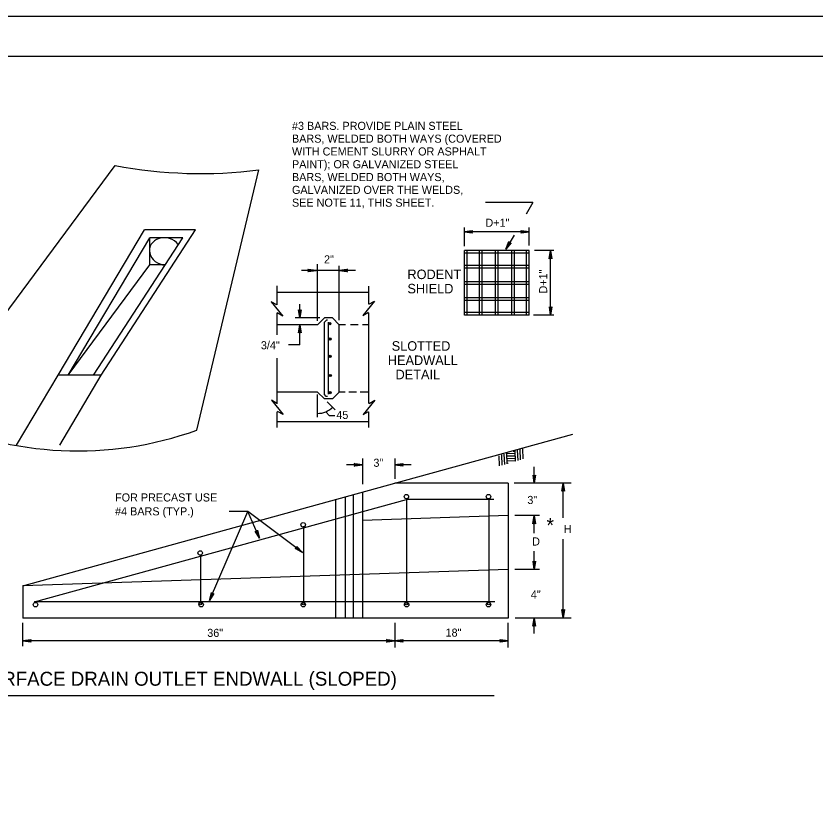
# Model space of a CAD drawing. Extents: x 638877 to 639960, y 297341 to 299123.
# Drawn here: x 639038.7 to 639335.5, y 298830 to 299123.3 of the extents above; entities that cross this region are included whole.
import ezdxf

# ---------------------------------------------------------------- set-up
doc = ezdxf.new("R2010")
doc.units = 0
for name, color, linetype in [('1', 7, 'Continuous'), ('2', 7, 'Continuous'), ('3', 7, 'Continuous'), ('PLT-BNDY', 7, 'Continuous')]:
    doc.layers.add(name, color=color, linetype=linetype)

msp = doc.modelspace()

# ---------------------------------------------------------------- linework, layer by layer
at = {"layer": '1'}
for p, q in [((639006.2, 298974.27), (639075.47, 299067.79)), ((639105.8, 298969.55), (639128.75, 299066.15)), ((639054.33, 298989.94), (639086.33, 299043.94)), ((639070.33, 298989.94), (639105.34, 299043.94)), ((639058.11, 298989.94), (639088.33, 299040.94)), ((639067.42, 298989.94), (639100.55, 299040.94)), ((639210.58, 299036.24), (639210.58, 299012.24)), ((639211.58, 299036.24), (639211.58, 299012.24)), ((639216.58, 299012.24), (639216.58, 299036.24)), ((639217.58, 299012.24), (639217.58, 299036.24)), ((639222.58, 299036.24), (639222.58, 299012.24)), ((639223.58, 299036.24), (639223.58, 299012.24)), ((639058.11, 298989.94), (639088.33, 299030.94)), ((639205.08, 299030.74), (639229.08, 299030.74)), ((639205.08, 299029.74), (639229.08, 299029.74)), ((639205.08, 299024.74), (639229.08, 299024.74)), ((639205.08, 299023.74), (639229.08, 299023.74)), ((639205.08, 299018.74), (639229.08, 299018.74)), ((639205.08, 299017.74), (639229.08, 299017.74)), ((639038.92, 298963.94), (639054.33, 298989.94)), ((639054.92, 298963.94), (639070.33, 298989.94)), ((639179.28, 298949.81), (639245.32, 298968)), ((639219.74, 298960.63), (639219.9, 298956.81)), ((639220.7, 298960.92), (639220.86, 298957.1)), ((639223.8, 298960.75), (639220.7, 298960.83)), ((639223.76, 298961.64), (639223.19, 298961.66)), ((639223.73, 298961.82), (639223.88, 298958)), ((639224.68, 298962.1), (639224.84, 298958.28)), ((639225.64, 298962.38), (639225.8, 298958.56)), ((639226.6, 298962.67), (639226.76, 298958.85)), ((639217.83, 298960.07), (639217.98, 298956.31)), ((639218.78, 298960.35), (639218.94, 298956.53)), ((639223.84, 298959.85), (639220.74, 298959.94)), ((639223.88, 298958.96), (639220.78, 298959.03)), ((639223.91, 298958.06), (639220.81, 298958.14)), ((639221.31, 298957.23), (639220.85, 298957.24)), ((639041.28, 298911.81), (639179.28, 298949.81)), ((639045.64, 298905.81), (639183.56, 298943.79))]:
    msp.add_line(p, q, dxfattribs=at)
for points in [[(639703.19, 298544.28), (639703.19, 299108.28), (638917.19, 299108.28), (638917.19, 298544.28), (639703.19, 298544.28), (639703.19, 298570.64), (639503.19, 298570.64), (639503.19, 298635.32), (639703.19, 298635.32), (639703.19, 298664.28), (639503.19, 298664.28), (639503.19, 298544.28), (639581.99, 298544.28), (639581.99, 298570.64), (639581.99, 298544.28), (639658.99, 298544.28), (639658.99, 298570.64), (639658.99, 298558.33), (639703.19, 298558.33)], [(639135.43, 299016.01), (639133.38, 299017.14), (639137.68, 299011.81), (639135.63, 299013.04)], [(639169.65, 299016.32), (639171.7, 299017.45), (639167.4, 299012.11), (639169.45, 299013.35)], [(639135.53, 298979.5), (639133.48, 298980.63), (639137.78, 298975.3), (639135.73, 298976.53)], [(639169.75, 298979.5), (639171.8, 298980.63), (639167.5, 298975.3), (639169.55, 298976.53)]]:
    msp.add_lwpolyline(points, dxfattribs=at)
for centre, radius in [((639155.12, 299009.11), 0.426), ((639155.12, 299009.11), 0.396), ((639155.12, 299009.11), 0.366), ((639155.12, 299009.11), 0.335), ((639155.12, 299009.11), 0.305), ((639155.12, 299009.11), 0.275), ((639155.12, 299009.11), 0.245), ((639155.12, 299009.11), 0.214), ((639155.12, 299009.11), 0.184), ((639155.12, 299009.11), 0.154), ((639155.12, 299009.11), 0.123), ((639155.12, 299009.11), 0.0932), ((639155.12, 299009.11), 0.063), ((639155.12, 299009.11), 0.0327), ((639155.22, 299003.37), 0.426), ((639155.22, 299003.37), 0.396), ((639155.22, 299003.37), 0.366), ((639155.22, 299003.37), 0.335), ((639155.22, 299003.37), 0.305), ((639155.22, 299003.37), 0.275), ((639155.22, 299003.37), 0.245), ((639155.22, 299003.37), 0.214), ((639155.22, 299003.37), 0.184), ((639155.22, 299003.37), 0.154), ((639155.22, 299003.37), 0.123), ((639155.22, 299003.37), 0.0932), ((639155.22, 299003.37), 0.063), ((639155.22, 299003.37), 0.0327), ((639155.22, 298996.91), 0.426), ((639155.22, 298996.91), 0.396), ((639155.22, 298996.91), 0.366), ((639155.22, 298996.91), 0.335), ((639155.22, 298996.91), 0.305), ((639155.22, 298996.91), 0.275), ((639155.22, 298996.91), 0.245), ((639155.22, 298996.91), 0.214), ((639155.22, 298996.91), 0.184), ((639155.22, 298996.91), 0.154), ((639155.22, 298996.91), 0.123), ((639155.22, 298996.91), 0.0932), ((639155.22, 298996.91), 0.063), ((639155.22, 298996.91), 0.0327), ((639155.33, 298989.83), 0.426), ((639155.33, 298989.83), 0.396), ((639155.33, 298989.83), 0.366), ((639155.33, 298989.83), 0.335), ((639155.33, 298989.83), 0.305), ((639155.33, 298989.83), 0.275), ((639155.33, 298989.83), 0.245), ((639155.33, 298989.83), 0.214), ((639155.33, 298989.83), 0.184), ((639155.33, 298989.83), 0.154), ((639155.33, 298989.83), 0.123), ((639155.33, 298989.83), 0.0932), ((639155.33, 298989.83), 0.063), ((639155.33, 298989.83), 0.0327), ((639155.22, 298983.48), 0.426), ((639155.22, 298983.48), 0.396), ((639155.22, 298983.48), 0.366), ((639155.22, 298983.48), 0.335), ((639155.22, 298983.48), 0.305), ((639155.22, 298983.48), 0.275), ((639155.22, 298983.48), 0.245), ((639155.22, 298983.48), 0.214), ((639155.22, 298983.48), 0.184), ((639155.22, 298983.48), 0.154), ((639155.22, 298983.48), 0.123), ((639155.22, 298983.48), 0.0932), ((639155.22, 298983.48), 0.063), ((639155.22, 298983.48), 0.0327), ((639183.56, 298944.89), 0.83), ((639214.01, 298944.89), 0.83), ((639145.25, 298934.42), 0.83), ((639107.06, 298923.96), 0.83), ((639045.96, 298904.75), 0.83), ((639107.42, 298904.75), 0.83), ((639107.14, 298905.24), 0.538), ((639145.29, 298904.75), 0.83), ((639145.38, 298905.24), 0.538), ((639183.64, 298904.75), 0.83), ((639183.56, 298905.24), 0.538), ((639214.01, 298904.75), 0.83), ((639214.1, 298905.24), 0.538)]:
    msp.add_circle(centre, radius, dxfattribs=at)
for centre, radius, start, end in [((639107.29, 299235.03), 170.24, 259.2283, 277.2441), ((639150.61, 298983.69), 7.93, 269.6858, 315.094), ((639061.68, 299091.74), 129.91, 244.722, 289.8547)]:
    msp.add_arc(centre, radius, start, end, dxfattribs=at)
msp.add_ellipse((639094.09, 299035.9), major_axis=(-5.74, 1.32), ratio=0.856903, start_param=3.942118, end_param=8.042258, dxfattribs=at)
at = {"layer": '2'}
for p, q in [((639230.48, 299054.03), (639212.89, 299054.03)), ((639230.48, 299054.03), (639228, 299049.74)), ((639105.34, 299043.94), (639086.33, 299043.94)), ((639205.08, 299037.82), (639205.08, 299044.79)), ((639229.08, 299038.03), (639229.08, 299044.79)), ((639088.33, 299030.94), (639088.33, 299040.94)), ((639100.55, 299040.94), (639088.33, 299040.94)), ((639229.08, 299043.16), (639205.08, 299043.16)), ((639223.49, 299041.92), (639220.46, 299036.67)), ((639205.08, 299012.24), (639205.08, 299036.24)), ((639229.08, 299036.24), (639205.08, 299036.24)), ((639229.08, 299035.24), (639205.08, 299035.24)), ((639206.08, 299012.24), (639206.08, 299036.24)), ((639228.08, 299012.24), (639228.08, 299036.24)), ((639229.08, 299012.24), (639229.08, 299036.24)), ((639238.3, 299036.24), (639231.13, 299036.24)), ((639237.07, 299012.24), (639237.07, 299036.24)), ((639094.05, 299030.94), (639088.33, 299030.94)), ((639158.61, 299028.83), (639144.62, 299028.83)), ((639150.61, 299010.11), (639150.61, 299031.14)), ((639158.61, 299010.32), (639158.61, 299030.52)), ((639164.66, 299028.83), (639158.61, 299028.83)), ((639135.61, 299016.01), (639135.61, 299023.09)), ((639169.61, 299016.42), (639169.61, 299022.99)), ((639169.61, 299020.69), (639135.61, 299020.69)), ((639144.05, 299011.19), (639144.05, 299016.29)), ((639135.61, 299004.95), (639135.61, 299013.04)), ((639151.49, 299011.19), (639142.27, 299011.19)), ((639153.11, 299011.19), (639150.61, 299008.69)), ((639156.11, 299011.19), (639153.11, 299011.19)), ((639156.11, 299011.19), (639158.61, 299008.69)), ((639169.61, 298979.5), (639169.61, 299013.04)), ((639229.08, 299013.24), (639205.08, 299013.24)), ((639229.08, 299012.24), (639205.08, 299012.24)), ((639238.3, 299012.24), (639230.72, 299012.24)), ((639150.61, 299008.69), (639135.61, 299008.69)), ((639144.05, 299001.18), (639144.05, 299008.69)), ((639153.86, 299010.35), (639153.11, 299009.6)), ((639153.11, 298982.73), (639153.11, 299009.6)), ((639154.31, 299010.35), (639153.86, 299010.35)), ((639154.61, 298982.89), (639154.61, 299009.6)), ((639158.61, 298983.69), (639158.61, 299008.69)), ((639161.02, 299008.69), (639158.61, 299008.69)), ((639165.63, 299008.69), (639162.76, 299008.69)), ((639169.61, 299008.69), (639167.27, 299008.69)), ((639144.05, 299001.18), (639139.83, 299001.18)), ((639135.61, 298979.3), (639135.61, 298996.29)), ((639070.33, 298989.94), (639054.33, 298989.94)), ((639150.61, 298983.69), (639135.61, 298983.69)), ((639150.61, 298983.69), (639153.11, 298981.19)), ((639150.61, 298974.33), (639150.61, 298982.73)), ((639153.83, 298982.08), (639153.14, 298982.77)), ((639154.28, 298982.08), (639153.83, 298982.08)), ((639158.61, 298983.69), (639156.11, 298981.19)), ((639160.81, 298983.69), (639158.61, 298983.69)), ((639165.01, 298983.69), (639162.15, 298983.69)), ((639169.61, 298983.69), (639166.45, 298983.69)), ((639156.11, 298981.19), (639153.11, 298981.19)), ((639154.19, 298980.11), (639157.17, 298977.14)), ((639135.61, 298970.48), (639135.61, 298976.33)), ((639153.63, 298976.32), (639155.07, 298974.88)), ((639169.61, 298970.58), (639169.61, 298976.33)), ((639169.61, 298972.69), (639135.61, 298972.69)), ((639157.02, 298974.88), (639155.07, 298974.88)), ((639167.28, 298959.01), (639167.28, 298949.51)), ((639179.28, 298959.01), (639179.28, 298951.49)), ((639167.28, 298956.65), (639161.33, 298956.65)), ((639185.38, 298956.65), (639179.28, 298956.65)), ((639231.01, 298949.81), (639231.01, 298955.95)), ((639221.28, 298949.81), (639179.28, 298949.81)), ((639221.28, 298949.81), (639221.28, 298899.81)), ((639244.66, 298949.81), (639223.5, 298949.81)), ((639241.7, 298936.97), (639241.7, 298949.92)), ((639167.28, 298946.5), (639167.28, 298899.81)), ((639157.28, 298943.75), (639157.28, 298899.81)), ((639160.78, 298944.71), (639160.78, 298899.81)), ((639163.78, 298945.54), (639163.78, 298899.81)), ((639183.56, 298944.34), (639183.56, 298905.24)), ((639216, 298943.79), (639183.56, 298943.79)), ((639214.1, 298943.79), (639214.1, 298905.81)), ((639110.45, 298906.29), (639124.78, 298939.37)), ((639124.78, 298939.37), (639117.76, 298939.37)), ((639129.08, 298929.4), (639124.78, 298939.37)), ((639144.99, 298924.16), (639124.78, 298939.37)), ((639221.28, 298937.81), (639167.28, 298936.01)), ((639232.99, 298937.81), (639223.78, 298937.81)), ((639231.01, 298931.32), (639231.01, 298937.81)), ((639145.38, 298933.85), (639145.38, 298905.24)), ((639241.7, 298899.92), (639241.7, 298929.12)), ((639107.16, 298923.33), (639107.16, 298905.24)), ((639231.01, 298917.81), (639231.01, 298924.59)), ((639221.28, 298917.81), (639041.28, 298911.81)), ((639232.99, 298917.81), (639223.78, 298917.81)), ((639041.28, 298911.81), (639041.28, 298899.81)), ((639216.32, 298905.81), (639045.64, 298905.81)), ((639221.28, 298899.81), (639041.28, 298899.81)), ((639244.66, 298899.81), (639223.9, 298899.81)), ((639231.01, 298894.07), (639231.01, 298899.81)), ((639041.28, 298889.32), (639041.28, 298898.02)), ((639179.28, 298898.02), (639179.28, 298888.92)), ((639221.28, 298888.92), (639221.28, 298898.02)), ((639179.28, 298891.31), (639041.28, 298891.31)), ((639221.28, 298891.31), (639179.28, 298891.31))]:
    msp.add_line(p, q, dxfattribs=at)
for points in [[(639207.98, 299042.79), (639207.87, 299043), (639205.08, 299043.16), (639207.98, 299042.79), (639208.13, 299042.66), (639205.08, 299043.16), (639207.87, 299043.29), (639207.97, 299043.5), (639205.08, 299043.16), (639208.13, 299043.64), (639207.97, 299043.5)], [(639226.18, 299043.52), (639226.29, 299043.31), (639229.08, 299043.16), (639226.18, 299043.52), (639226.03, 299043.65), (639229.08, 299043.16), (639226.29, 299043.02), (639226.19, 299042.81), (639229.08, 299043.16), (639226.03, 299042.67), (639226.19, 299042.81)], [(639222.22, 299039), (639221.99, 299039.01), (639220.46, 299036.67), (639222.22, 299039), (639222.41, 299039.06), (639220.46, 299036.67), (639221.73, 299039.15), (639221.6, 299039.34), (639220.46, 299036.67), (639221.56, 299039.55), (639221.6, 299039.34)], [(639236.71, 299033.34), (639236.92, 299033.45), (639237.07, 299036.24), (639236.71, 299033.34), (639236.58, 299033.2), (639237.07, 299036.24), (639237.21, 299033.45), (639237.42, 299033.35), (639237.07, 299036.24), (639237.55, 299033.2), (639237.42, 299033.35)], [(639147.16, 299029.2), (639147.26, 299028.99), (639150.05, 299028.83), (639147.16, 299029.2), (639147.01, 299029.32), (639150.05, 299028.83), (639147.27, 299028.69), (639147.16, 299028.49), (639150.05, 299028.83), (639147.01, 299028.35), (639147.16, 299028.49)], [(639161.51, 299028.47), (639161.4, 299028.68), (639158.61, 299028.83), (639161.51, 299028.47), (639161.66, 299028.34), (639158.61, 299028.83), (639161.4, 299028.97), (639161.5, 299029.18), (639158.61, 299028.83), (639161.66, 299029.32), (639161.5, 299029.18)], [(639144.42, 299014.09), (639144.21, 299013.99), (639144.05, 299011.19), (639144.42, 299014.09), (639144.54, 299014.24), (639144.05, 299011.19), (639143.91, 299013.98), (639143.71, 299014.08), (639144.05, 299011.19), (639143.57, 299014.24), (639143.71, 299014.08)], [(639237.43, 299015.14), (639237.22, 299015.04), (639237.07, 299012.24), (639237.43, 299015.14), (639237.56, 299015.29), (639237.07, 299012.24), (639236.93, 299015.03), (639236.72, 299015.13), (639237.07, 299012.24), (639236.59, 299015.29), (639236.72, 299015.13)], [(639143.69, 299005.79), (639143.9, 299005.9), (639144.05, 299008.69), (639143.69, 299005.79), (639143.56, 299005.65), (639144.05, 299008.69), (639144.19, 299005.9), (639144.4, 299005.8), (639144.05, 299008.69), (639144.54, 299005.65), (639144.4, 299005.8)], [(639164.38, 298957.01), (639164.49, 298956.8), (639167.28, 298956.65), (639164.38, 298957.01), (639164.23, 298957.14), (639167.28, 298956.65), (639164.49, 298956.51), (639164.39, 298956.3), (639167.28, 298956.65), (639164.23, 298956.16), (639164.39, 298956.3)], [(639182.18, 298956.28), (639182.07, 298956.49), (639179.28, 298956.65), (639182.18, 298956.28), (639182.33, 298956.16), (639179.28, 298956.65), (639182.07, 298956.79), (639182.17, 298956.99), (639179.28, 298956.65), (639182.33, 298957.13), (639182.17, 298956.99)], [(639231.38, 298952.71), (639231.17, 298952.6), (639231.01, 298949.81), (639231.38, 298952.71), (639231.5, 298952.86), (639231.01, 298949.81), (639230.87, 298952.6), (639230.67, 298952.7), (639231.01, 298949.81), (639230.53, 298952.86), (639230.67, 298952.7)], [(639241.33, 298947.02), (639241.54, 298947.13), (639241.7, 298949.92), (639241.33, 298947.02), (639241.2, 298946.87), (639241.7, 298949.92), (639241.83, 298947.13), (639242.04, 298947.03), (639241.7, 298949.92), (639242.18, 298946.87), (639242.04, 298947.03)], [(639230.65, 298934.91), (639230.86, 298935.02), (639231.01, 298937.81), (639230.65, 298934.91), (639230.52, 298934.76), (639231.01, 298937.81), (639231.15, 298935.02), (639231.36, 298934.92), (639231.01, 298937.81), (639231.5, 298934.76), (639231.36, 298934.92)], [(639128.27, 298932.21), (639128.12, 298932.03), (639129.08, 298929.4), (639128.27, 298932.21), (639128.33, 298932.39), (639129.08, 298929.4), (639127.85, 298931.91), (639127.62, 298931.92), (639129.08, 298929.4), (639127.43, 298932.01), (639127.62, 298931.92)], [(639142.89, 298926.19), (639142.85, 298925.96), (639144.99, 298924.16), (639142.89, 298926.19), (639142.85, 298926.38), (639144.99, 298924.16), (639142.68, 298925.73), (639142.47, 298925.62), (639144.99, 298924.16), (639142.27, 298925.6), (639142.47, 298925.62)], [(639231.38, 298920.71), (639231.17, 298920.6), (639231.01, 298917.81), (639231.38, 298920.71), (639231.5, 298920.86), (639231.01, 298917.81), (639230.87, 298920.6), (639230.67, 298920.7), (639231.01, 298917.81), (639230.53, 298920.86), (639230.67, 298920.7)], [(639111.94, 298908.81), (639111.71, 298908.79), (639110.45, 298906.29), (639111.94, 298908.81), (639112.12, 298908.89), (639110.45, 298906.29), (639111.44, 298908.91), (639111.29, 298909.08), (639110.45, 298906.29), (639111.22, 298909.28), (639111.29, 298909.08)], [(639242.06, 298902.82), (639241.85, 298902.71), (639241.7, 298899.92), (639242.06, 298902.82), (639242.19, 298902.97), (639241.7, 298899.92), (639241.56, 298902.71), (639241.35, 298902.81), (639241.7, 298899.92), (639241.21, 298902.97), (639241.35, 298902.81)], [(639230.65, 298896.91), (639230.86, 298897.02), (639231.01, 298899.81), (639230.65, 298896.91), (639230.52, 298896.76), (639231.01, 298899.81), (639231.15, 298897.02), (639231.36, 298896.92), (639231.01, 298899.81), (639231.5, 298896.76), (639231.36, 298896.92)], [(639044.18, 298890.95), (639044.07, 298891.16), (639041.28, 298891.31), (639044.18, 298890.95), (639044.33, 298890.82), (639041.28, 298891.31), (639044.07, 298891.45), (639044.17, 298891.66), (639041.28, 298891.31), (639044.33, 298891.79), (639044.17, 298891.66)], [(639176.38, 298891.67), (639176.49, 298891.46), (639179.28, 298891.31), (639176.38, 298891.67), (639176.23, 298891.8), (639179.28, 298891.31), (639176.49, 298891.17), (639176.39, 298890.96), (639179.28, 298891.31), (639176.23, 298890.83), (639176.39, 298890.96)], [(639182.18, 298890.95), (639182.07, 298891.16), (639179.28, 298891.31), (639182.18, 298890.95), (639182.33, 298890.82), (639179.28, 298891.31), (639182.07, 298891.45), (639182.17, 298891.66), (639179.28, 298891.31), (639182.33, 298891.79), (639182.17, 298891.66)], [(639218.38, 298891.67), (639218.49, 298891.46), (639221.28, 298891.31), (639218.38, 298891.67), (639218.23, 298891.8), (639221.28, 298891.31), (639218.49, 298891.17), (639218.39, 298890.96), (639221.28, 298891.31), (639218.23, 298890.83), (639218.39, 298890.96)]]:
    msp.add_lwpolyline(points, dxfattribs=at)
at = {"layer": '3'}
msp.add_line((639006.92, 298871.03), (639216.12, 298871.03), dxfattribs=at)
at = {"layer": 'PLT-BNDY'}
msp.add_lwpolyline([(638877.19, 299123.28), (639718.19, 299123.28), (639718.19, 298529.28), (638877.19, 298529.28)], close=True, dxfattribs=at)

# ---------------------------------------------------------------- texts
at = {"layer": '1'}
for s, height, p in [('#3 BARS. PROVIDE PLAIN STEEL', 3, (639141.1, 299081)), ('BARS, WELDED BOTH WAYS (COVERED ', 3, (639141.1, 299076.25)), ('WITH CEMENT SLURRY OR ASPHALT', 3, (639141.1, 299071.5)), ('PAINT); OR GALVANIZED STEEL ', 3, (639141.1, 299066.75)), ('BARS, WELDED BOTH WAYS, ', 3, (639141.1, 299062)), ('GALVANIZED OVER THE WELDS, ', 3, (639141.1, 299057.25)), ('SEE NOTE 11, THIS SHEET.', 3, (639141.1, 299052.5)), ('D+1"', 3, (639212.86, 299045.03)), ('2"', 3, (639152.99, 299031.44)), ('RODENT', 3.53, (639183.94, 299025.62)), ('SHIELD', 3.53, (639183.94, 299020.32)), ('3/4"', 3, (639129.57, 298999.56)), ('SLOTTED', 3.53, (639178.1, 298999.03)), ('HEADWALL', 3.53, (639176.67, 298993.73)), ('DETAIL', 3.53, (639179.53, 298988.44)), ('45', 3, (639157.55, 298973.71)), ('3"', 3, (639171.31, 298955.95)), ('3"', 3, (639228.42, 298942.14)), ('H', 3, (639241.97, 298931.38)), ('D', 3, (639230.22, 298926.73)), ('4"', 3, (639229.72, 298907.05)), ('36"', 3, (639109.67, 298892.8)), ('18"', 3, (639198.08, 298892.9))]:
    msp.add_text(s, height=height, dxfattribs=at).set_placement(p)
msp.add_text('D+1"', height=3, rotation=90, dxfattribs=at).set_placement((639235.79, 299020.27))
at = {"layer": '3'}
for s, height, p in [('FOR PRECAST USE', 3, (639075.47, 298943.07)), ('#4 BARS (TYP.)', 3, (639075.47, 298937.91)), ('*', 5.4, (639235.52, 298931.55)), ('SUBSURFACE DRAIN OUTLET ENDWALL (SLOPED)', 5.186, (639009.71, 298874.68))]:
    msp.add_text(s, height=height, dxfattribs=at).set_placement(p)

doc.saveas('drawing.dxf')
